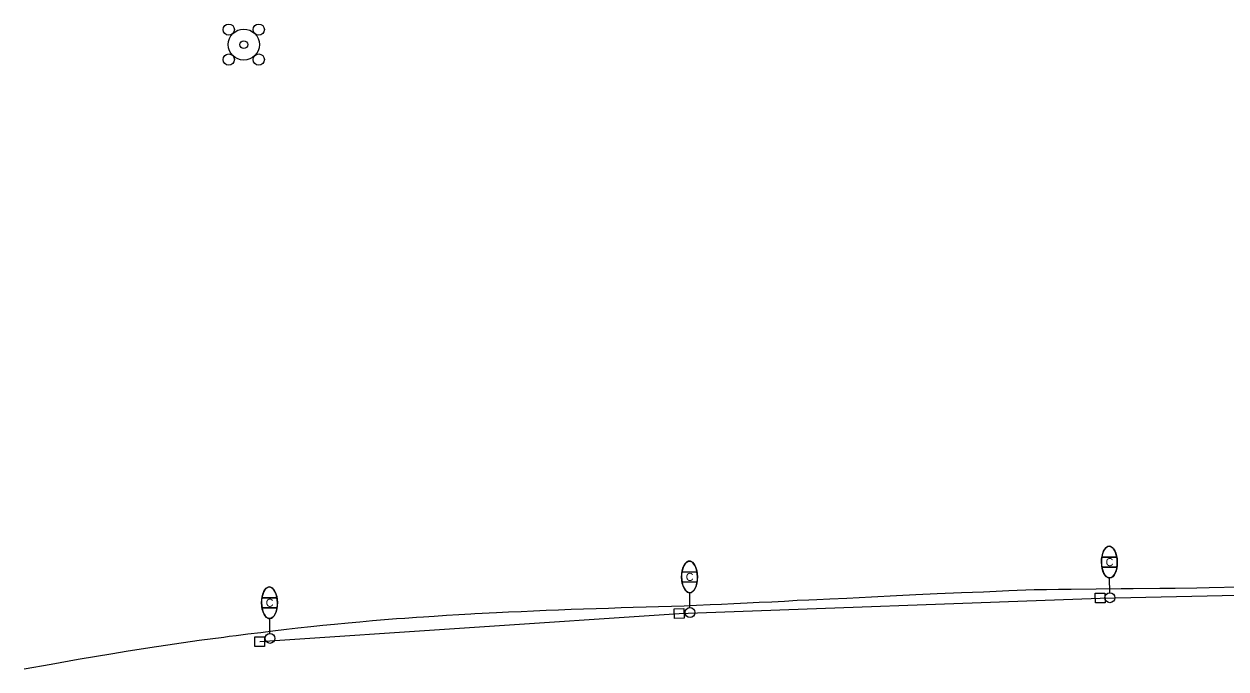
# Model space of a CAD drawing. Extents: x 915723 to 927758, y 636394 to 638609.
# Drawn here: x 920575 to 921176, y 636865 to 637188 of the extents above; entities that cross this region are included whole.
import ezdxf

# ---------------------------------------------------------------- set-up
doc = ezdxf.new("R2010")
doc.units = 0
for name, color, linetype in [('ConduitOT', 7, 'Continuous'), ('DrShaftConc', 7, 'Continuous'), ('Miscellaneous2', 7, 'Continuous'), ('PoleLight', 7, 'Continuous'), ('PoleLightHM_ep', 7, 'Continuous'), ('PullBox', 7, 'Continuous'), ('TextStructuresLabel', 7, 'Continuous')]:
    doc.layers.add(name, color=color, linetype=linetype)

msp = doc.modelspace()

# ---------------------------------------------------------------- linework, layer by layer
at = {"layer": 'ConduitOT'}
for p, q in [((921113.17, 636900.91), (921322.78, 636905.12)), ((920902.78, 636893.18), (921113.17, 636900.91)), ((920693.15, 636879.09), (920902.78, 636893.18))]:
    msp.add_line(p, q, dxfattribs=at)
at = {"layer": 'DrShaftConc'}
msp.add_lwpolyline([(920575.37, 636865.43), (920588.9, 636867.81), (920602.35, 636870.33), (920619.66, 636873.22), (920626.48, 636874.34), (920638.28, 636876.17), (920650.54, 636877.97), (920662.93, 636879.79), (920675.18, 636881.42), (920677.92, 636881.81), (920681.3, 636882.25), (920687.28, 636882.99), (920693.71, 636883.75), (920699.7, 636884.49), (920706.56, 636885.29), (920712.24, 636885.93), (920718.69, 636886.59), (920724.74, 636887.29), (920730.48, 636887.81), (920737.32, 636888.46), (920743.11, 636889.04), (920749.59, 636889.59), (920755.47, 636890.13), (920761.48, 636890.61), (920765.68, 636890.88), (920771.55, 636891.35), (920774.97, 636891.54), (920780.34, 636891.88), (920786.52, 636892.33), (920792.7, 636892.69), (920798.69, 636893.01), (920800.59, 636893.14), (920811.5, 636893.73), (920817.41, 636893.96), (920823.81, 636894.25), (920830.04, 636894.58), (920836.25, 636894.82), (920842.44, 636895.06), (920848.78, 636895.28), (920854.99, 636895.49), (920861.26, 636895.69), (920867.54, 636895.87), (920873.86, 636896.1), (920879.71, 636896.29), (920886.3, 636896.49), (920892.5, 636896.62), (920898.93, 636896.83), (920905.32, 636897.07), (920911.41, 636897.34), (920918.28, 636897.66), (920923.89, 636897.87), (920930.11, 636898.15), (920936.8, 636898.49), (920942.69, 636898.77), (920949.03, 636899.09), (920955.4, 636899.4), (920961.68, 636899.79), (920967.58, 636900.03), (920971.52, 636900.13), (920978.07, 636900.47), (920986.63, 636900.91), (920998.86, 636901.5), (921011.45, 636902.14), (921021.06, 636902.61), (921031.77, 636903.12), (921043.9, 636903.6), (921054.82, 636904.07), (921067.48, 636904.61), (921080.13, 636905.11), (921086.32, 636905.17), (921092.4, 636905.27), (921098.6, 636905.31), (921111.16, 636905.52), (921123.59, 636905.64), (921129.75, 636905.61), (921142.93, 636905.8), (921150.58, 636905.8), (921161.56, 636905.94), (921167.71, 636906.11), (921197.98, 636906.8)], dxfattribs=at)
at = {"layer": 'Miscellaneous2'}
for p, q in [((921121.51, 636921.42), (921114, 636921.32)), ((921114.06, 636916.32), (921121.58, 636916.42)), ((921121.51, 636921.42), (921121.51, 636921.42)), ((921121.58, 636916.42), (921121.58, 636916.42)), ((920911.68, 636914.01), (920904.16, 636913.91)), ((920911.68, 636914.01), (920911.68, 636914.01)), ((920904.23, 636908.91), (920911.75, 636909.01)), ((920911.75, 636909.01), (920911.75, 636909.01)), ((920701.76, 636901.09), (920694.25, 636900.98)), ((920701.76, 636901.09), (920701.76, 636901.09)), ((920694.31, 636895.99), (920701.83, 636896.09)), ((920701.83, 636896.09), (920701.83, 636896.09))]:
    msp.add_line(p, q, dxfattribs=at)
for centre, start_param, end_param in [((921117.79, 636918.87), 4.391271, 5.033538), ((921117.79, 636918.87), 4.391241, 4.391271), ((921117.79, 636918.87), 1.249648, 1.891946), ((920907.95, 636911.46), 4.391271, 5.033538), ((920907.95, 636911.46), 4.391241, 4.391271), ((920907.95, 636911.46), 1.249648, 1.891946), ((920698.04, 636898.54), 4.391271, 5.033538), ((920698.04, 636898.54), 4.391241, 4.391271), ((920698.04, 636898.54), 1.249648, 1.891946)]:
    msp.add_ellipse(centre, major_axis=(0.11, -7.92), ratio=0.5, start_param=start_param, end_param=end_param, dxfattribs=at)
at = {"layer": 'PoleLight'}
for p, q in [((921114, 636921.32), (921121.51, 636921.42)), ((921121.58, 636916.42), (921114.06, 636916.32)), ((920904.16, 636913.91), (920911.68, 636914.01)), ((921117.99, 636903.53), (921117.89, 636910.95)), ((920911.75, 636909.01), (920904.23, 636908.91)), ((920908.16, 636896.11), (920908.06, 636903.54)), ((920694.25, 636900.98), (920701.76, 636901.09)), ((920701.83, 636896.09), (920694.31, 636895.99)), ((920698.24, 636883.19), (920698.14, 636890.62))]:
    msp.add_line(p, q, dxfattribs=at)
for centre in [(921118.03, 636901.05), (921118.03, 636901.05), (920908.19, 636893.64), (920908.19, 636893.64), (920698.28, 636880.72), (920698.28, 636880.72)]:
    msp.add_circle(centre, 2.48, dxfattribs=at)
for centre in [(921117.79, 636918.87), (920907.95, 636911.46), (920698.04, 636898.54)]:
    msp.add_ellipse(centre, major_axis=(0.11, -7.92), ratio=0.5, dxfattribs=at)
for centre, start_param, end_param in [((921117.79, 636918.87), 1.891945, 4.391241), ((920907.95, 636911.46), 1.891945, 4.391241), ((921117.79, 636918.87), 5.033538, 6.283185), ((921117.79, 636918.87), 0.847605, 1.249648), ((921117.79, 636918.87), 0, 0.847605), ((920698.04, 636898.54), 1.891945, 4.391241), ((920907.95, 636911.46), 5.033538, 6.283185), ((920907.95, 636911.46), 0, 0.847605), ((920907.95, 636911.46), 0.847605, 1.249648), ((920698.04, 636898.54), 5.033538, 6.283185), ((920698.04, 636898.54), 0, 0.847605), ((920698.04, 636898.54), 0.847605, 1.249648)]:
    msp.add_ellipse(centre, major_axis=(0.11, -7.92), ratio=0.5, start_param=start_param, end_param=end_param, dxfattribs=at)
at = {"layer": 'PoleLightHM_ep'}
for centre, radius in [((920677.68, 637185.19), 2.81), ((920692.67, 637185.19), 2.81), ((920685.18, 637177.7), 7.79), ((920685.18, 637177.7), 1.95), ((920677.68, 637170.2), 2.81), ((920692.67, 637170.2), 2.81)]:
    msp.add_circle(centre, radius, dxfattribs=at)
at = {"layer": 'PullBox'}
for p, q in [((921110.73, 636903.27), (921115.53, 636903.36)), ((921110.82, 636898.47), (921110.73, 636903.27)), ((921115.62, 636898.55), (921110.82, 636898.47)), ((921115.53, 636903.36), (921115.62, 636898.55)), ((920900.34, 636895.54), (920905.14, 636895.62)), ((920900.42, 636890.74), (920900.34, 636895.54)), ((920905.14, 636895.62), (920905.23, 636890.82)), ((920905.23, 636890.82), (920900.42, 636890.74)), ((920690.71, 636881.45), (920695.51, 636881.53)), ((920690.79, 636876.65), (920690.71, 636881.45)), ((920695.51, 636881.53), (920695.6, 636876.73)), ((920695.6, 636876.73), (920690.79, 636876.65))]:
    msp.add_line(p, q, dxfattribs=at)

# ---------------------------------------------------------------- texts
at = {"layer": 'TextStructuresLabel'}
for p in [(921115.94, 636916.85), (920906.11, 636909.43), (920696.19, 636896.51)]:
    msp.add_text('C', height=4, rotation=0.76701, dxfattribs=at).set_placement(p)

doc.saveas('drawing.dxf')
